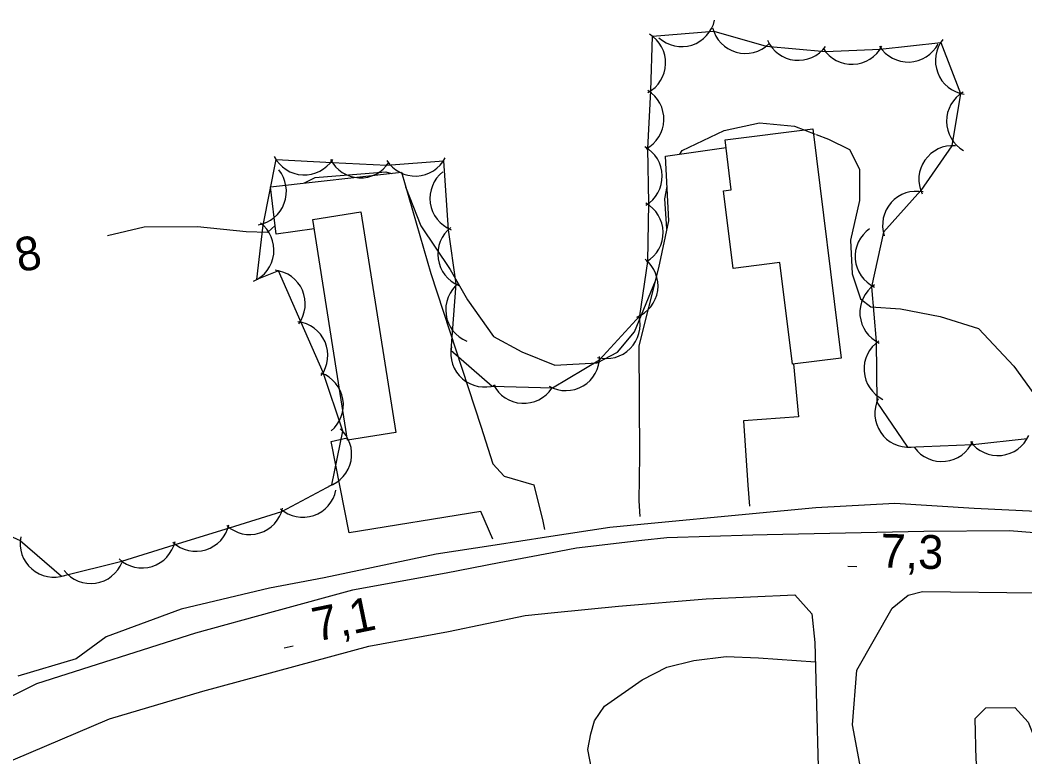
# Model space of a CAD drawing. Extents: x 643342 to 646936, y 5873857 to 5876103.
# Drawn here: x 645086.4 to 645175.6, y 5874287.8 to 5874353.2 of the extents above; entities that cross this region are included whole.
import ezdxf

# ---------------------------------------------------------------- set-up
doc = ezdxf.new("R2010")
doc.units = 0
for name, color, linetype in [('Niveau 19', 7, 'Continuous'), ('Niveau 2', 7, 'Continuous'), ('Niveau 21', 7, 'Continuous'), ('Niveau 3', 7, 'Continuous'), ('Niveau 31', 7, 'Continuous'), ('Niveau 4', 7, 'Continuous'), ('Niveau 44', 7, 'Continuous')]:
    doc.layers.add(name, color=color, linetype=linetype)

msp = doc.modelspace()

# ---------------------------------------------------------------- linework, layer by layer
at = {"layer": 'Niveau 19'}
for points in [[(645141.413, 5874309.14), (645141.319, 5874310.526), (645141.396, 5874314.528), (645141.315, 5874324.274), (645143.065, 5874331.21), (645143.951, 5874335.385), (645143.675, 5874341.123), (645149.049, 5874341.889)], [(645112.477, 5874334.671), (645109.11, 5874334.202), (645108.587, 5874338.396), (645120.22, 5874339.676), (645122.829, 5874330.691), (645127.275, 5874317.137), (645128.324, 5874313.803), (645129.338, 5874312.699), (645131.968, 5874311.943), (645132.776, 5874308.709), (645132.938, 5874307.977)], [(645155.027, 5874322.671), (645155.476, 5874317.969), (645150.58, 5874317.627), (645150.972, 5874311.898), (645151.115, 5874310.04)], [(645128.325, 5874307.109), (645127.286, 5874309.559), (645115.574, 5874307.681), (645113.975, 5874315.787), (645115.412, 5874316.117)], [(645139.72, 5874273.074), (645136.782, 5874288.441), (645137.026, 5874289.833), (645137.358, 5874290.976), (645138.26, 5874292.278), (645141.585, 5874294.621), (645143.8, 5874295.747), (645146.171, 5874296.35), (645149.049, 5874296.702), (645151.917, 5874296.593), (645156.981, 5874296.217)]]:
    msp.add_lwpolyline(points, dxfattribs=at)
at = {"layer": 'Niveau 2'}
for points in [[(645144.941, 5874341.303), (645145.142, 5874341.606), (645148.884, 5874343.394), (645152, 5874344.081), (645155.124, 5874343.77), (645156.951, 5874343.076)], [(645157.049, 5874343.039), (645158.13, 5874342.628), (645160.008, 5874341.702), (645160.889, 5874339.943), (645160.902, 5874337.184), (645160.089, 5874333.662), (645160.234, 5874330.678), (645160.972, 5874328.439), (645161.898, 5874327.741), (645164.544, 5874327.573), (645168.044, 5874326.878), (645171.452, 5874325.824), (645174.607, 5874322.464), (645176.355, 5874320.003)], [(645111.629, 5874338.731), (645112.554, 5874339.219), (645118.85, 5874339.717), (645119.349, 5874339.581)], [(645120.596, 5874338.381), (645121.932, 5874334.937), (645124.541, 5874331.065), (645126.075, 5874328.353), (645128.407, 5874325.108), (645130.901, 5874323.756), (645133.854, 5874322.552), (645137.589, 5874322.754), (645139.398, 5874323.703), (645140.914, 5874325.512), (645142.768, 5874330.033)], [(645143.8, 5874334.675), (645143.619, 5874337.33), (645143.806, 5874338.414)], [(645094.141, 5874334.061), (645097.379, 5874334.842), (645102.126, 5874334.879), (645106.437, 5874334.415), (645108.374, 5874334.374), (645109.016, 5874334.954)]]:
    msp.add_lwpolyline(points, dxfattribs=at)
at = {"layer": 'Niveau 21'}
for points in [[(645184.44, 5874307.035), (645174.201, 5874307.844), (645166.596, 5874307.781), (645152.68, 5874307.511), (645151.411, 5874307.472), (645143.796, 5874307.241), (645141.565, 5874306.987), (645135.773, 5874306.326), (645133.469, 5874305.884), (645128.895, 5874305.006), (645124.203, 5874304.106), (645115.865, 5874302.581), (645108.842, 5874300.678), (645101.934, 5874298.783), (645087.815, 5874294.266), (645081.234, 5874290.982)], [(645085.765, 5874287.513), (645094.315, 5874291.17), (645102.591, 5874293.632), (645117.331, 5874297.604), (645124.394, 5874298.922), (645131.214, 5874300.341), (645133.815, 5874300.597), (645139.481, 5874301.155), (645147.286, 5874301.82), (645155.161, 5874302.179), (645156.645, 5874300.496), (645156.937, 5874297.931), (645157.08, 5874292.419), (645157.222, 5874286.907)], [(645161.745, 5874282.753), (645160.269, 5874290.637), (645160.641, 5874295.479), (645163.779, 5874300.985), (645165.222, 5874302.143), (645166.488, 5874302.467), (645176.45, 5874302.343)]]:
    msp.add_lwpolyline(points, dxfattribs=at)
at = {"layer": 'Niveau 3'}
for p, q in [((645159.847, 5874304.716), (645160.647, 5874304.694)), ((645109.817, 5874297.47), (645110.6, 5874297.632))]:
    msp.add_line(p, q, dxfattribs=at)
at = {"layer": 'Niveau 31'}
for points in [[(645156.758, 5874343.53), (645159.263, 5874323.193), (645154.928, 5874322.659), (645153.819, 5874331.659), (645149.68, 5874331.149), (645148.831, 5874338.047), (645149.512, 5874338.131), (645148.965, 5874342.57), (645156.758, 5874343.53)], [(645116.633, 5874336.173), (645119.731, 5874316.587), (645115.445, 5874315.909), (645112.346, 5874335.495), (645116.633, 5874336.173)]]:
    msp.add_lwpolyline(points, dxfattribs=at)
at = {"layer": 'Niveau 4'}
msp.add_lwpolyline([(645187.045, 5874309.077), (645171.074, 5874309.837), (645164.017, 5874310.283), (645157.015, 5874309.91), (645151.394, 5874309.372), (645141.463, 5874308.421), (645138.739, 5874308.16), (645133.09, 5874307.291), (645128.545, 5874306.592), (645123.313, 5874305.787), (645113.374, 5874303.68), (645108.511, 5874302.752), (645100.661, 5874300.909), (645094.024, 5874298.444), (645091.342, 5874296.492), (645086.165, 5874294.953)], dxfattribs=at)
at = {"layer": 'Niveau 44'}
for points in [[(645133.629, 5874320.546), (645137.806, 5874323.019), (645141.402, 5874326.947), (645142.094, 5874331.752), (645142.174, 5874336.929), (645142.095, 5874341.782), (645142.366, 5874346.912), (645142.515, 5874351.764), (645147.945, 5874352.197), (645152.613, 5874350.865), (645157.861, 5874350.411), (645162.712, 5874350.6), (645168.107, 5874351.213), (645169.865, 5874346.688), (645169.096, 5874342.041), (645166.326, 5874338.054), (645163.012, 5874334.351), (645161.961, 5874329.499), (645162.373, 5874324.662), (645162.42, 5874319.285), (645165.167, 5874315.282), (645170.943, 5874315.525), (645175.77, 5874316.039)], [(645081.584, 5874309.169), (645086.382, 5874307.005), (645090.042, 5874303.816), (645095.404, 5874305.162), (645100.04, 5874306.601), (645104.955, 5874308.123), (645109.591, 5874309.562), (645114.059, 5874311.931), (645115.021, 5874316.689), (645113.281, 5874321.908), (645111.331, 5874326.353), (645109.324, 5874330.933), (645107.377, 5874330.15), (645107.938, 5874334.972), (645109.093, 5874340.803), (645114.087, 5874340.552), (645118.935, 5874340.31), (645123.955, 5874340.69), (645124.366, 5874334.571), (645125.046, 5874329.765), (645124.616, 5874323.883), (645128.274, 5874320.693), (645133.629, 5874320.546)], [(645180.206, 5874265.862), (645175.73, 5874267.838), (645174.288, 5874270.263), (645173.052, 5874274.146), (645171.26, 5874287.514), (645171.158, 5874291.183), (645172.098, 5874292.14), (645174.687, 5874292.174), (645175.868, 5874290.88), (645180.744, 5874278.692), (645184.261, 5874270.585), (645184.445, 5874267.991), (645184.005, 5874266.935), (645182.003, 5874266.076), (645180.206, 5874265.862)]]:
    msp.add_lwpolyline(points, dxfattribs=at)
for centre, start, end in [((645145.101, 5874353.834), 227.60443, 347.58238), ((645145.101, 5874353.834), 227.60443, 347.58238), ((645145.101, 5874353.834), 227.60443, 347.58238), ((645150.763, 5874353.226), 194.07667, 314.05462), ((645150.763, 5874353.226), 194.07667, 314.05462), ((645150.763, 5874353.226), 194.07667, 314.05462), ((645140.678, 5874349.392), 298.24397, 58.22192), ((645140.678, 5874349.392), 298.24397, 58.22192), ((645140.678, 5874349.392), 298.24397, 58.22192), ((645155.456, 5874352.618), 203.95851, 323.93646), ((645155.456, 5874352.618), 203.95851, 323.93646), ((645155.456, 5874352.618), 203.95851, 323.93646), ((645170.629, 5874349.589), 141.23133, 261.20928), ((645170.629, 5874349.589), 141.23133, 261.20928), ((645170.629, 5874349.589), 141.23133, 261.20928), ((645160.218, 5874352.268), 212.2317, 332.20964), ((645160.218, 5874352.268), 212.2317, 332.20964), ((645160.218, 5874352.268), 212.2317, 332.20964), ((645165.214, 5874352.461), 212.2317, 332.20964), ((645165.214, 5874352.461), 212.2317, 332.20964), ((645165.214, 5874352.461), 212.2317, 332.20964), ((645140.523, 5874344.395), 298.24397, 58.22192), ((645140.523, 5874344.395), 298.24397, 58.22192), ((645140.523, 5874344.395), 298.24397, 58.22192), ((645171.617, 5874344.218), 120.35864, 240.33659), ((645171.617, 5874344.218), 120.35864, 240.33659), ((645171.617, 5874344.218), 120.35864, 240.33659), ((645140.371, 5874339.327), 300.93368, 60.91163), ((645140.371, 5874339.327), 300.93368, 60.91163), ((645140.371, 5874339.327), 300.93368, 60.91163), ((645169.159, 5874339.042), 85.21523, 205.19318), ((645169.159, 5874339.042), 85.21523, 205.19318), ((645169.159, 5874339.042), 85.21523, 205.19318), ((645111.605, 5874342.443), 207.14328, 327.12122), ((645111.605, 5874342.443), 207.14328, 327.12122), ((645111.605, 5874342.443), 207.14328, 327.12122), ((645116.598, 5874342.192), 207.14328, 327.12122), ((645116.598, 5874342.192), 207.14328, 327.12122), ((645116.598, 5874342.192), 207.14328, 327.12122), ((645121.452, 5874342.345), 212.53179, 332.50973), ((645121.452, 5874342.345), 212.53179, 332.50973), ((645121.452, 5874342.345), 212.53179, 332.50973), ((645107.016, 5874337.974), 279.57276, 39.5507), ((645107.016, 5874337.974), 279.57276, 39.5507), ((645107.016, 5874337.974), 279.57276, 39.5507), ((645125.753, 5874337.366), 128.05847, 248.03641), ((645125.753, 5874337.366), 128.05847, 248.03641), ((645125.753, 5874337.366), 128.05847, 248.03641), ((645165.942, 5874334.995), 78.38678, 198.36472), ((645165.942, 5874334.995), 78.38678, 198.36472), ((645165.942, 5874334.995), 78.38678, 198.36472), ((645140.451, 5874334.327), 300.93368, 60.91163), ((645140.451, 5874334.327), 300.93368, 60.91163), ((645140.451, 5874334.327), 300.93368, 60.91163), ((645105.906, 5874332.765), 293.36255, 53.34049), ((645105.906, 5874332.765), 293.36255, 53.34049), ((645105.906, 5874332.765), 293.36255, 53.34049), ((645126.452, 5874332.415), 128.05847, 248.03641), ((645126.452, 5874332.415), 128.05847, 248.03641), ((645126.452, 5874332.415), 128.05847, 248.03641), ((645163.502, 5874332.212), 124.86376, 244.84171), ((645163.502, 5874332.212), 124.86376, 244.84171), ((645163.502, 5874332.212), 124.86376, 244.84171), ((645140.003, 5874329.601), 291.8026, 51.78055), ((645140.003, 5874329.601), 291.8026, 51.78055), ((645140.003, 5874329.601), 291.8026, 51.78055), ((645108.684, 5874328.002), 323.68422, 83.66216), ((645108.684, 5874328.002), 323.68422, 83.66216), ((645108.684, 5874328.002), 323.68422, 83.66216), ((645127.151, 5874327.465), 128.05847, 248.03641), ((645127.151, 5874327.465), 128.05847, 248.03641), ((645127.151, 5874327.465), 128.05847, 248.03641), ((645163.924, 5874327.23), 124.86376, 244.84171), ((645163.924, 5874327.23), 124.86376, 244.84171), ((645163.924, 5874327.23), 124.86376, 244.84171), ((645110.691, 5874323.422), 323.68422, 83.66216), ((645110.691, 5874323.422), 323.68422, 83.66216), ((645110.691, 5874323.422), 323.68422, 83.66216), ((645138.407, 5874326.143), 255.245, 15.22295), ((645138.407, 5874326.143), 255.245, 15.22295), ((645138.407, 5874326.143), 255.245, 15.22295), ((645164.29, 5874322.219), 123.92776, 243.9057), ((645164.29, 5874322.219), 123.92776, 243.9057), ((645164.29, 5874322.219), 123.92776, 243.9057), ((645127.604, 5874323.617), 168.90911, 288.88706), ((645127.604, 5874323.617), 168.90911, 288.88706), ((645127.604, 5874323.617), 168.90911, 288.88706), ((645134.819, 5874323.3), 240.62756, 0.60551), ((645134.819, 5874323.3), 240.62756, 0.60551), ((645134.819, 5874323.3), 240.62756, 0.60551), ((645112.072, 5874319.035), 309.74661, 69.72455), ((645112.072, 5874319.035), 309.74661, 69.72455), ((645112.072, 5874319.035), 309.74661, 69.72455), ((645131.073, 5874322.169), 206.69299, 326.67094), ((645131.073, 5874322.169), 206.69299, 326.67094), ((645131.073, 5874322.169), 206.69299, 326.67094), ((645165.248, 5874318.281), 154.45853, 274.43648), ((645165.248, 5874318.281), 154.45853, 274.43648), ((645165.248, 5874318.281), 154.45853, 274.43648), ((645112.811, 5874314.66), 288.56917, 48.54712), ((645112.811, 5874314.66), 288.56917, 48.54712), ((645112.811, 5874314.66), 288.56917, 48.54712), ((645168.197, 5874317.009), 216.0749, 336.05285), ((645168.197, 5874317.009), 216.0749, 336.05285), ((645168.197, 5874317.009), 216.0749, 336.05285), ((645173.17, 5874317.536), 216.0749, 336.05285), ((645173.17, 5874317.536), 216.0749, 336.05285), ((645173.17, 5874317.536), 216.0749, 336.05285), ((645111.465, 5874312.057), 228.878, 348.85594), ((645111.465, 5874312.057), 228.878, 348.85594), ((645111.465, 5874312.057), 228.878, 348.85594), ((645106.75, 5874310.527), 227.24566, 347.22361), ((645106.75, 5874310.527), 227.24566, 347.22361), ((645106.75, 5874310.527), 227.24566, 347.22361), ((645101.975, 5874309.046), 227.24566, 347.22361), ((645101.975, 5874309.046), 227.24566, 347.22361), ((645101.975, 5874309.046), 227.24566, 347.22361), ((645089.371, 5874306.74), 168.93551, 288.91346), ((645089.371, 5874306.74), 168.93551, 288.91346), ((645089.371, 5874306.74), 168.93551, 288.91346), ((645097.199, 5874307.566), 227.24566, 347.22361), ((645097.199, 5874307.566), 227.24566, 347.22361), ((645097.199, 5874307.566), 227.24566, 347.22361), ((645092.645, 5874306.184), 218.11832, 338.09626), ((645092.645, 5874306.184), 218.11832, 338.09626), ((645092.645, 5874306.184), 218.11832, 338.09626)]:
    msp.add_arc(centre, 3, start, end, dxfattribs=at)

# ---------------------------------------------------------------- texts
at = {"layer": 'Niveau 2'}
msp.add_text('8', height=3, rotation=11.73661, dxfattribs=at).set_placement((645086.28, 5874330.78))
at = {"layer": 'Niveau 3'}
for s, height, rotation, p in [('7,3  ', 3, 358.40957, (645162.72, 5874304.6)), ('7,1  ', 2.9999, 11.66681, (645112.65, 5874298.01))]:
    msp.add_text(s, height=height, rotation=rotation, dxfattribs=at).set_placement(p)

doc.saveas('drawing.dxf')
